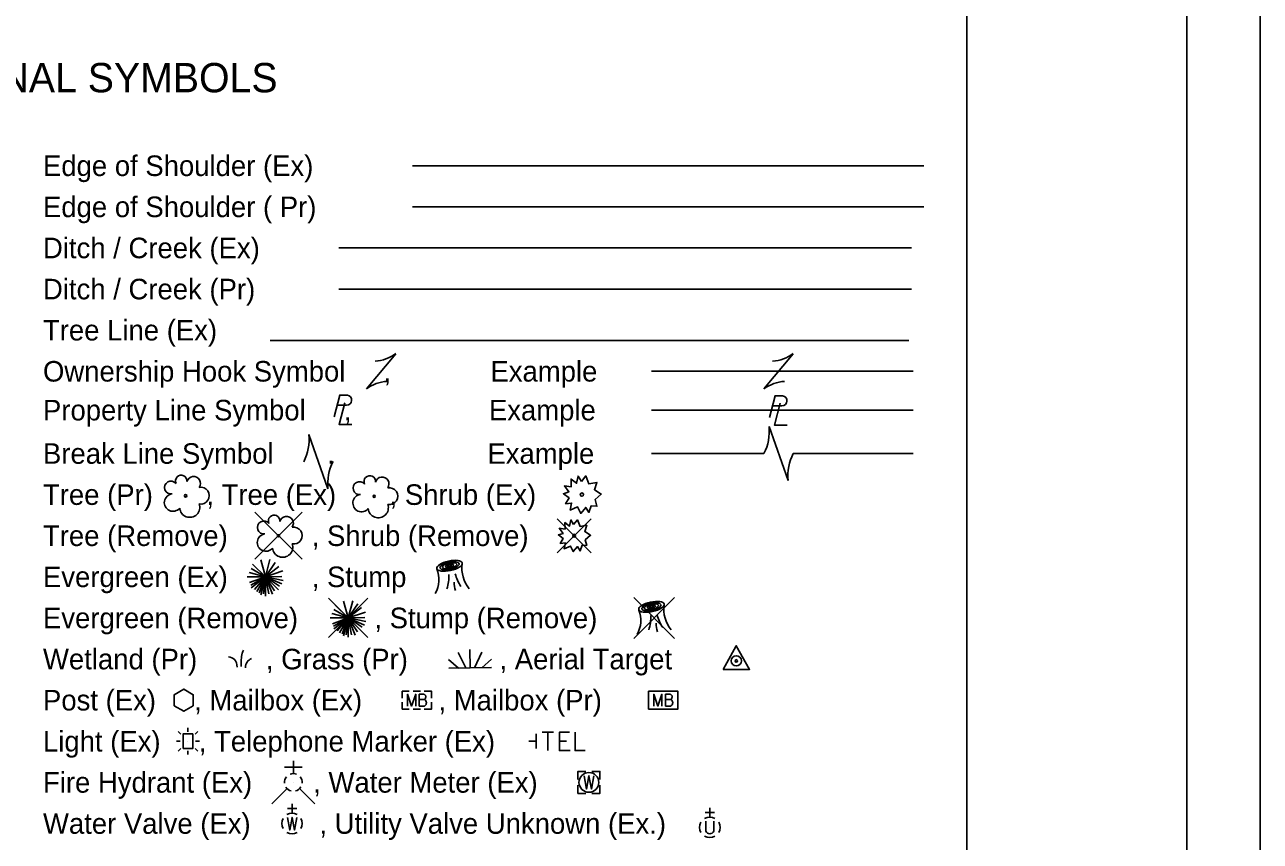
# Model space of a CAD drawing. Extents: x 0 to 34, y 0 to 22.
# Drawn here: x 25.58 to 34, y 5.44 to 11 of the extents above; entities that cross this region are included whole.
import ezdxf

# ---------------------------------------------------------------- set-up
doc = ezdxf.new("R2010")
doc.units = 0
for name, color, linetype in [('SH_Border', 7, 'Continuous'), ('SH_Cut_Line', 7, 'Continuous'), ('SH_Text', 7, 'Continuous')]:
    doc.layers.add(name, color=color, linetype=linetype)

msp = doc.modelspace()

# ---------------------------------------------------------------- linework, layer by layer
at = {"layer": 'SH_Border'}
msp.add_line((32, 0.5), (32, 21.5), dxfattribs=at)
msp.add_lwpolyline([(1.5, 21.5), (33.5, 21.5), (33.5, 0.5), (1.5, 0.5)], close=True, dxfattribs=at)
at = {"layer": 'SH_Cut_Line'}
msp.add_lwpolyline([(0, 0), (34, 0), (34, 22), (0, 22)], close=True, dxfattribs=at)
at = {"layer": 'SH_Text'}
for p, q in [((28.2234, 10.0395), (31.7067, 10.0395)), ((28.2234, 9.7595), (31.7067, 9.7595)), ((27.723, 9.4795), (31.623, 9.4795)), ((27.723, 9.1995), (31.623, 9.1995)), ((27.2553, 8.8495), (31.6053, 8.8495)), ((27.9103, 8.5195), (28.1103, 8.7595)), ((30.6185, 8.5195), (30.8185, 8.7595)), ((28.0103, 8.6395), (28.0103, 8.6395)), ((29.8531, 8.6395), (31.6353, 8.6395)), ((30.7185, 8.6395), (30.7185, 8.6395)), ((27.7106, 8.4085), (27.7754, 8.4085)), ((27.7507, 8.3774), (27.7507, 8.3774)), ((29.8531, 8.3749), (31.6353, 8.3749)), ((30.6762, 8.4044), (30.741, 8.4044)), ((30.7163, 8.3733), (30.7163, 8.3733)), ((30.6535, 8.2637), (30.7835, 7.8955)), ((27.5179, 8.2081), (27.6479, 7.8398)), ((27.5829, 8.024), (27.5829, 8.024)), ((29.8531, 8.0795), (30.6186, 8.0795)), ((30.7185, 8.0796), (30.7185, 8.0796)), ((30.8184, 8.0795), (31.6353, 8.0795)), ((27.1507, 7.6799), (27.4715, 7.3591)), ((27.4715, 7.6799), (27.1507, 7.3591)), ((29.2098, 7.6354), (29.4416, 7.4037)), ((29.4416, 7.6354), (29.2098, 7.4037)), ((27.3111, 7.5195), (27.3111, 7.5195)), ((29.3257, 7.5196), (29.3257, 7.5196)), ((27.2216, 7.2393), (27.1343, 7.3265)), ((27.2216, 7.2393), (27.1907, 7.3546)), ((27.2216, 7.2393), (27.253, 7.3568)), ((27.2216, 7.2393), (27.2879, 7.3364)), ((27.2216, 7.2393), (27.1112, 7.2689)), ((27.2216, 7.2393), (27.1239, 7.2967)), ((27.2216, 7.2393), (27.313, 7.3094)), ((27.2216, 7.2393), (27.34, 7.2795)), ((27.2216, 7.2393), (27.3343, 7.2416)), ((28.4952, 7.2395), (28.4952, 7.2395)), ((27.0982, 7.2393), (27.2216, 7.2393)), ((27.2216, 7.2393), (27.1143, 7.2003)), ((27.2216, 7.2393), (27.122, 7.1823)), ((27.2216, 7.2393), (27.1239, 7.1644)), ((27.2216, 7.2393), (27.1479, 7.1526)), ((27.2216, 7.2393), (27.1636, 7.1389)), ((27.2216, 7.2393), (27.1799, 7.1308)), ((27.2216, 7.2393), (27.19, 7.1179)), ((27.2216, 7.2393), (27.208, 7.1245)), ((27.2216, 7.1083), (27.2216, 7.2393)), ((27.2216, 7.2393), (27.2446, 7.1234)), ((27.2216, 7.2393), (27.2699, 7.1226)), ((27.2216, 7.2393), (27.285, 7.1445)), ((27.2216, 7.2393), (27.3113, 7.1513)), ((27.2216, 7.2393), (27.3171, 7.1754)), ((27.2216, 7.2393), (27.3332, 7.1908)), ((27.2216, 7.2393), (27.3423, 7.2154)), ((27.6519, 7.0932), (27.9192, 6.8259)), ((27.9192, 7.0932), (27.6519, 6.8259)), ((27.7856, 6.9595), (27.7547, 7.0749)), ((27.7856, 6.9595), (27.817, 7.077)), ((29.7318, 7.0986), (30.0098, 6.8205)), ((30.0098, 7.0986), (29.7318, 6.8205)), ((27.7856, 6.9595), (27.6752, 6.9891)), ((27.7856, 6.9595), (27.6879, 7.017)), ((27.7856, 6.9595), (27.6983, 7.0467)), ((27.7856, 6.9595), (27.8519, 7.0567)), ((27.7856, 6.9595), (27.877, 7.0297)), ((27.7856, 6.9595), (27.904, 6.9997)), ((27.6622, 6.9595), (27.7856, 6.9595)), ((27.7856, 6.9595), (27.6783, 6.9205)), ((27.7856, 6.9595), (27.686, 6.9025)), ((27.7856, 6.9595), (27.6879, 6.8847)), ((27.7856, 6.9595), (27.7119, 6.8729)), ((27.7856, 6.9595), (27.7276, 6.8592)), ((27.7856, 6.9595), (27.7439, 6.851)), ((27.7856, 6.9595), (27.754, 6.8381)), ((27.7856, 6.9595), (27.772, 6.8447)), ((27.7856, 6.9595), (27.8983, 6.9618)), ((27.7856, 6.8285), (27.7856, 6.9595)), ((27.7856, 6.9595), (27.8086, 6.8436)), ((27.7856, 6.9595), (27.8339, 6.8428)), ((27.7856, 6.9595), (27.849, 6.8647)), ((27.7856, 6.9595), (27.8753, 6.8715)), ((27.7856, 6.9595), (27.8811, 6.8957)), ((27.7856, 6.9595), (27.8972, 6.911)), ((27.7856, 6.9595), (27.9063, 6.9356)), ((27.7856, 6.9595), (27.7856, 6.9595)), ((29.8708, 6.9596), (29.8708, 6.9596)), ((29.8708, 6.9595), (29.8708, 6.9595)), ((28.6172, 6.6196), (28.6153, 6.745)), ((28.5385, 6.6184), (28.4702, 6.6755)), ((28.5872, 6.6191), (28.5351, 6.7252)), ((28.6471, 6.62), (28.6961, 6.7276)), ((28.6959, 6.6207), (28.7624, 6.6798)), ((28.4711, 6.6174), (28.7633, 6.6217)), ((28.2283, 6.4606), (28.2784, 6.4606)), ((28.2539, 6.3995), (28.2539, 6.3995)), ((29.9321, 6.3995), (29.9321, 6.3995)), ((28.2283, 6.3385), (28.2784, 6.3385)), ((26.646, 6.168), (26.6275, 6.1867)), ((26.6943, 6.1835), (26.6943, 6.2101)), ((26.7609, 6.1867), (26.7424, 6.168)), ((29.0669, 6.0695), (29.0669, 6.1695)), ((26.6421, 6.1199), (26.6155, 6.1199)), ((26.646, 6.0711), (26.6275, 6.0524)), ((26.6943, 6.1195), (26.6943, 6.1195)), ((26.7609, 6.0524), (26.7424, 6.0711)), ((26.773, 6.1199), (26.7464, 6.1199)), ((29.0669, 6.1195), (29.0172, 6.1195)), ((26.6943, 6.0555), (26.6943, 6.029)), ((27.4123, 5.8997), (27.4123, 5.9857)), ((27.4723, 5.9427), (27.3523, 5.9427)), ((27.4124, 5.8395), (27.4124, 5.8395)), ((27.4124, 5.8395), (27.4124, 5.8395)), ((29.4259, 5.8395), (29.4259, 5.8395)), ((27.37, 5.7971), (27.266, 5.6932)), ((27.4546, 5.7971), (27.5586, 5.6932)), ((27.435, 5.6614), (27.3714, 5.6614)), ((27.4032, 5.6295), (27.4032, 5.6931)), ((30.2494, 5.6032), (30.2494, 5.6667)), ((27.4032, 5.5595), (27.4032, 5.5595)), ((30.2811, 5.6349), (30.2176, 5.6349)), ((30.2222, 5.5762), (30.2222, 5.5073)), ((30.2765, 5.5762), (30.2765, 5.5073)), ((30.2494, 5.5332), (30.2494, 5.5332))]:
    msp.add_line(p, q, dxfattribs=at)
for points in [[(27.6896, 8.329), (27.7287, 8.4772), (27.7803, 8.4771)], [(27.764, 8.4254), (27.7244, 8.2775), (27.8117, 8.2775)], [(30.6552, 8.3249), (30.6943, 8.4731), (30.746, 8.473)], [(30.7296, 8.4213), (30.69, 8.2734), (30.7774, 8.2734)], [(29.3744, 7.89), (29.4047, 7.9268), (29.4254, 7.8741), (29.48, 7.8831), (29.4631, 7.8325), (29.5103, 7.8028), (29.4675, 7.766), (29.48, 7.7204), (29.4423, 7.7238), (29.4261, 7.6781), (29.4047, 7.7127), (29.3708, 7.6719), (29.3493, 7.7162), (29.2983, 7.6947), (29.3079, 7.7418), (29.2673, 7.7376), (29.291, 7.7771), (29.2526, 7.8055), (29.2895, 7.8187), (29.2592, 7.8589), (29.3058, 7.8534), (29.3043, 7.9053), (29.3419, 7.8769), (29.3523, 7.9261), (29.3744, 7.89)], [(29.3221, 7.5965), (29.3478, 7.6277), (29.3654, 7.5829), (29.4118, 7.5906), (29.3974, 7.5476), (29.4376, 7.5223), (29.4012, 7.4911), (29.4118, 7.4522), (29.3798, 7.4552), (29.366, 7.4163), (29.3478, 7.4457), (29.319, 7.411), (29.3008, 7.4487), (29.2574, 7.4304), (29.2656, 7.4705), (29.2311, 7.4669), (29.2512, 7.5005), (29.2185, 7.5246), (29.2499, 7.5358), (29.2241, 7.57), (29.2637, 7.5653), (29.2624, 7.6094), (29.2945, 7.5853), (29.3032, 7.6271), (29.3221, 7.5965)], [(26.6011, 6.362), (26.666, 6.3245), (26.7309, 6.362), (26.7309, 6.437), (26.666, 6.4745), (26.6011, 6.437), (26.6011, 6.362)], [(28.1539, 6.4121), (28.1539, 6.4606), (28.2024, 6.4606)], [(28.1891, 6.3595), (28.1891, 6.4395), (28.2181, 6.3595), (28.2458, 6.4395), (28.2458, 6.3595)], [(28.305, 6.403), (28.3082, 6.4061), (28.3101, 6.408), (28.3113, 6.4099), (28.3119, 6.4112), (28.3132, 6.4137), (28.3138, 6.4156), (28.3151, 6.42), (28.3151, 6.4219), (28.3151, 6.4244), (28.3145, 6.4282), (28.3132, 6.4313), (28.3113, 6.4339), (28.3082, 6.4364), (28.3056, 6.4376), (28.3044, 6.4383), (28.3012, 6.4395), (28.2704, 6.4395), (28.2704, 6.3595), (28.305, 6.3595), (28.3094, 6.3621), (28.3132, 6.3652), (28.3164, 6.3703), (28.3182, 6.3759), (28.3189, 6.3816), (28.3189, 6.3854), (28.3176, 6.3891), (28.3151, 6.3948), (28.3119, 6.3986), (28.305, 6.403), (28.2704, 6.403)], [(28.3043, 6.4606), (28.3539, 6.4606), (28.3539, 6.4121)], [(29.8672, 6.3595), (29.8672, 6.4395), (29.8962, 6.3595), (29.9239, 6.4395), (29.9239, 6.3595)], [(29.9831, 6.403), (29.9863, 6.4061), (29.9882, 6.408), (29.9894, 6.4099), (29.9901, 6.4112), (29.9913, 6.4137), (29.992, 6.4156), (29.9932, 6.42), (29.9932, 6.4219), (29.9932, 6.4244), (29.9926, 6.4282), (29.9913, 6.4313), (29.9894, 6.4339), (29.9863, 6.4364), (29.9838, 6.4376), (29.9825, 6.4383), (29.9794, 6.4395), (29.9485, 6.4395), (29.9485, 6.3595), (29.9831, 6.3595), (29.9875, 6.3621), (29.9913, 6.3652), (29.9945, 6.3703), (29.9964, 6.3759), (29.997, 6.3816), (29.997, 6.3854), (29.9957, 6.3891), (29.9932, 6.3948), (29.9901, 6.3986), (29.9831, 6.403), (29.9485, 6.403)], [(28.2024, 6.3385), (28.1539, 6.3385), (28.1539, 6.387)], [(28.3539, 6.387), (28.3539, 6.3385), (28.3043, 6.3385)], [(29.1077, 6.1816), (29.1855, 6.1816)], [(29.1471, 6.1816), (29.1471, 6.0566)], [(29.2928, 6.1816), (29.2248, 6.1816), (29.2248, 6.0566), (29.2977, 6.0566)], [(29.3321, 6.1816), (29.3321, 6.0566), (29.4, 6.0566)], [(29.2248, 6.1196), (29.2731, 6.1196)], [(29.4059, 5.9145), (29.3509, 5.9145), (29.3509, 5.8595)], [(29.5009, 5.8595), (29.5009, 5.9145), (29.4459, 5.9145)], [(29.3509, 5.8195), (29.3509, 5.7645), (29.4059, 5.7645)], [(29.3926, 5.8845), (29.4093, 5.7945), (29.4259, 5.8845), (29.4426, 5.7945), (29.4593, 5.8845)], [(29.4459, 5.7645), (29.5009, 5.7645), (29.5009, 5.8195)], [(27.3714, 5.6005), (27.3873, 5.5144), (27.4032, 5.6005), (27.4192, 5.5144), (27.4351, 5.6005)]]:
    msp.add_lwpolyline(points, dxfattribs=at)
for points in [[(30.3402, 6.6095), (30.5202, 6.6095), (30.4302, 6.7705)], [(29.8321, 6.4606), (30.0321, 6.4606), (30.0321, 6.3385), (29.8321, 6.3385)], [(26.6609, 6.0695), (26.7275, 6.0695), (26.7275, 6.1695), (26.6609, 6.1695)]]:
    msp.add_lwpolyline(points, close=True, dxfattribs=at)
for centre, radius in [((26.6781, 7.7914), 0.0084), ((27.9627, 7.788), 0.0072), ((29.3786, 7.7996), 0.0115), ((27.3111, 7.5195), 0.0072), ((29.3257, 7.5196), 0.00979), ((30.4302, 6.6674), 0.035), ((30.4302, 6.6674), 0.008), ((29.4259, 5.8395), 0.0675)]:
    msp.add_circle(centre, radius, dxfattribs=at)
for centre, radius, start, end in [((27.9522, 8.9745), 0.2668, 273.69448, 306.33701), ((30.6604, 8.9745), 0.2668, 273.69448, 306.33701), ((28.0684, 8.3046), 0.2668, 93.69448, 126.33701), ((30.7766, 8.3046), 0.2668, 93.69448, 126.33701), ((27.7751, 8.443), 0.0345, 270.47098, 81.3281), ((30.7408, 8.4389), 0.0345, 270.47098, 81.3281), ((30.3216, 8.2313), 0.3335, 332.94224, 5.58476), ((27.1859, 8.1756), 0.3335, 332.94224, 5.58476), ((27.9798, 7.8723), 0.3335, 152.94224, 185.58476), ((31.1155, 7.9279), 0.3335, 152.94224, 185.58476), ((26.6485, 7.8925), 0.0395, 354.0047, 205.97412), ((26.7328, 7.8763), 0.0466, 323.82996, 165.0376), ((27.9331, 7.889), 0.0395, 354.0047, 205.97412), ((28.0174, 7.8728), 0.0466, 323.82996, 165.0376), ((26.5788, 7.8473), 0.0441, 39.06254, 279.54124), ((26.7819, 7.7925), 0.0574, 259.14531, 101.45961), ((27.8634, 7.8439), 0.0441, 39.06254, 279.54124), ((28.0665, 7.7891), 0.0574, 259.14531, 101.45961), ((26.5925, 7.745), 0.0592, 96.17219, 320.57371), ((27.8771, 7.7415), 0.0592, 96.17219, 320.57371), ((26.7064, 7.7133), 0.0685, 184.94757, 19.45715), ((27.9911, 7.7098), 0.0685, 184.94757, 19.45715), ((27.2118, 7.5754), 0.0441, 39.06254, 279.54124), ((27.2816, 7.6205), 0.0395, 354.0047, 205.97412), ((27.3659, 7.6044), 0.0466, 323.82996, 165.0376), ((27.4149, 7.5206), 0.0574, 259.14531, 101.45961), ((27.2255, 7.473), 0.0592, 96.17219, 320.57371), ((27.3395, 7.4414), 0.0685, 184.94757, 19.45715), ((28.7755, 7.2966), 0.2146, 171.41061, 219.91939), ((28.2036, 7.2222), 0.2001, 331.53375, 20.92689), ((28.2194, 7.2408), 0.2527, 340.79377, 3.54808), ((28.8206, 7.3424), 0.316, 194.9653, 212.12159), ((28.6905, 7.1995), 0.1819, 178.79264, 197.12241), ((29.5792, 6.9422), 0.2001, 331.53375, 20.92689), ((30.1511, 7.0166), 0.2146, 171.41061, 219.91939), ((29.5949, 6.9608), 0.2527, 340.79377, 3.54808), ((30.0661, 6.9195), 0.1819, 178.79264, 197.12241), ((30.1962, 7.0624), 0.316, 194.9653, 212.12159), ((27.4124, 5.8395), 0.06, 68.13946, 112.03798), ((27.4124, 5.8395), 0.06, 140.02099, 184.06293), ((27.4124, 5.8395), 0.06, 283.82389, 329.90967), ((27.4124, 5.8395), 0.06, 356.01648, 39.98885), ((27.4124, 5.8395), 0.06, 211.87877, 255.84793), ((27.4032, 5.5596), 0.07, 150.01836, 209.98164), ((27.4032, 5.5596), 0.07, 60.01836, 120.01574), ((27.4032, 5.5596), 0.07, 330.01836, 29.98164), ((30.2494, 5.5332), 0.07, 150.01836, 209.98164), ((30.2494, 5.5332), 0.07, 60.01836, 120.01574), ((30.2494, 5.5332), 0.07, 330.01836, 29.98164), ((27.4032, 5.5596), 0.07, 239.98426, 299.98164), ((30.2494, 5.5332), 0.07, 239.98426, 299.98164), ((30.2493, 5.5201), 0.03, 205.19243, 334.80757)]:
    msp.add_arc(centre, radius, start, end, dxfattribs=at)
for centre, major_axis in [((28.4765, 7.3151), (0.0868, 0.0187)), ((28.4765, 7.3151), (0.0651, 0.0141)), ((28.4765, 7.3151), (0.0488, 0.0105)), ((28.4765, 7.3151), (0.0275, 0.0059)), ((28.4765, 7.3151), (0.0154, 0.0033)), ((29.8521, 7.0351), (0.0868, 0.0187)), ((29.8521, 7.0351), (0.0651, 0.0141)), ((29.8521, 7.0351), (0.0488, 0.0105)), ((29.8521, 7.0351), (0.0275, 0.0059)), ((29.8521, 7.0351), (0.0154, 0.0033))]:
    msp.add_ellipse(centre, major_axis=major_axis, ratio=0.36865, dxfattribs=at)
for points in [[(27.0576, 6.6281), (27.0576, 6.6754), (27.0636, 6.7199), (27.0724, 6.7406)], [(26.9703, 6.6951), (27.0117, 6.6774), (27.0295, 6.6241)], [(27.0854, 6.6209), (27.0972, 6.6594), (27.1267, 6.6831)]]:
    msp.add_spline(points, degree=3, dxfattribs=at)

# ---------------------------------------------------------------- texts
for s, height, p in [('CONVENTIONAL SYMBOLS', 0.2, (23.8272, 10.5395)), ('Edge of Shoulder (Ex)', 0.14, (25.7067, 9.9695)), ('Edge of Shoulder ( Pr)', 0.14, (25.7067, 9.6895)), ('Ditch / Creek (Ex)', 0.14, (25.7067, 9.4095)), ('Ditch / Creek (Pr)', 0.14, (25.7067, 9.1295)), ('Tree Line (Ex)', 0.14, (25.7067, 8.8495)), ('Ownership Hook Symbol     ,             Example', 0.14, (25.7067, 8.5695)), ('Property Line Symbol     ,                  Example', 0.14, (25.7067, 8.3049)), ('Break Line Symbol       ,                    Example', 0.14, (25.7067, 8.0095)), ('Tree (Pr)       , Tree (Ex)       , Shrub (Ex)', 0.14, (25.7067, 7.7295)), ('Tree (Remove)           , Shrub (Remove)', 0.14, (25.7067, 7.4495)), ('Evergreen (Ex)           , Stump ', 0.14, (25.7067, 7.1695)), ('Evergreen (Remove)          , Stump (Remove)', 0.14, (25.7067, 6.8895)), ('Wetland (Pr)         , Grass (Pr)            , Aerial Target    ', 0.14, (25.7067, 6.6095)), ('Post (Ex)     , Mailbox (Ex)          , Mailbox (Pr)', 0.14, (25.7067, 6.3295)), ('Light (Ex)     , Telephone Marker (Ex)     ', 0.14, (25.7067, 6.0495)), ('Fire Hydrant (Ex)        , Water Meter (Ex)', 0.14, (25.7067, 5.7695)), ('Water Valve (Ex)         , Utility Valve Unknown (Ex.)', 0.14, (25.7067, 5.4895))]:
    msp.add_text(s, height=height, dxfattribs=at).set_placement(p)

doc.saveas('drawing.dxf')
